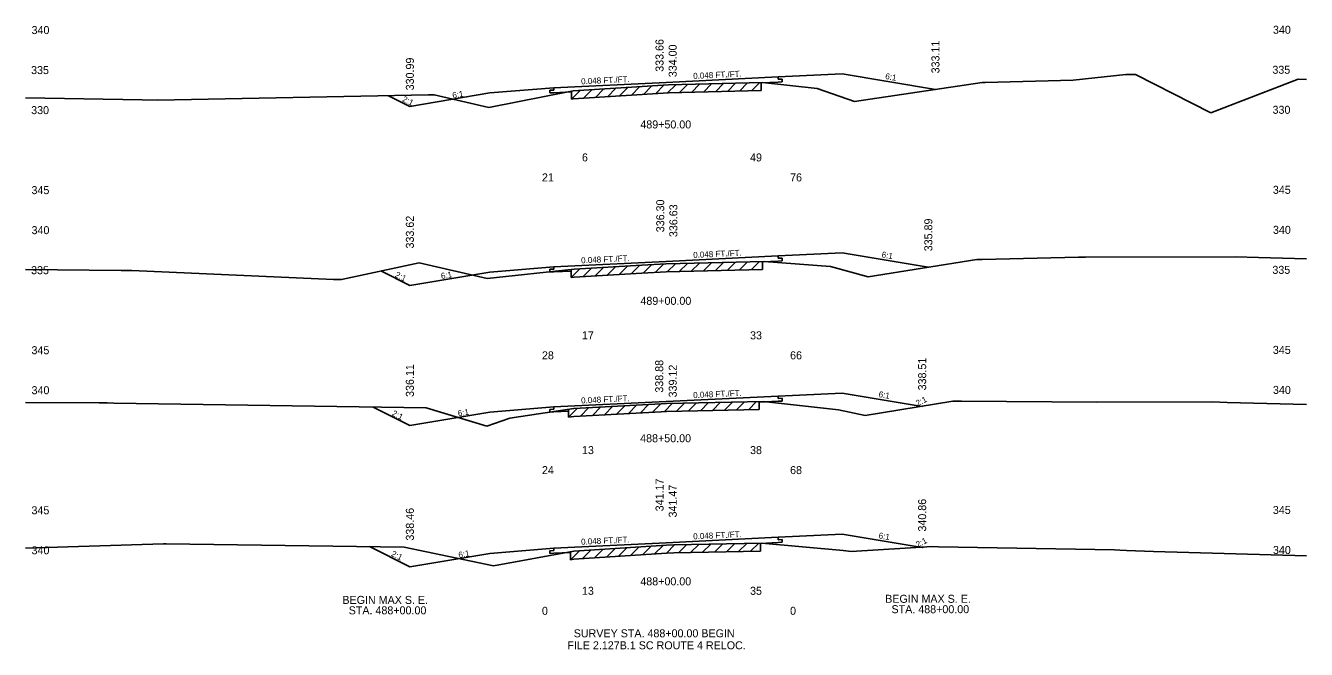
# Model space of a CAD drawing. Extents: x 2967 to 4323, y -3677 to -817.
# Drawn here: x 3188.8 to 3348.8, y -3676.7 to -3598.8 of the extents above; entities that cross this region are included whole.
import ezdxf

# ---------------------------------------------------------------- set-up
doc = ezdxf.new("R2010")
doc.units = 0
for name, color, linetype in [('Level 1', 7, 'Continuous'), ('Level 10', 7, 'Continuous'), ('Level 11', 7, 'Continuous'), ('Level 12', 7, 'Continuous'), ('Level 3', 7, 'Continuous'), ('Level 32', 7, 'Continuous'), ('Level 33', 7, 'Continuous'), ('Level 59', 7, 'Continuous'), ('Level 6', 7, 'Continuous'), ('Level 60', 7, 'Continuous'), ('Level 61', 7, 'Continuous'), ('Level 7', 7, 'Continuous')]:
    doc.layers.add(name, color=color, linetype=linetype)

msp = doc.modelspace()

# ---------------------------------------------------------------- linework, layer by layer
at = {"layer": 'Level 11'}
for p, q in [((3282.76, -3605.47), (3282.76, -3605.17)), ((3283.26, -3605.45), (3282.76, -3605.47)), ((3282.76, -3605.81), (3283.26, -3605.79)), ((3283.26, -3605.79), (3283.26, -3605.45)), ((3254.76, -3606.82), (3254.26, -3606.84)), ((3254.26, -3606.84), (3254.26, -3607.18)), ((3254.26, -3607.18), (3254.76, -3607.16)), ((3254.76, -3606.52), (3254.76, -3606.82)), ((3282.76, -3627.84), (3282.76, -3627.54)), ((3283.26, -3627.82), (3282.76, -3627.84)), ((3282.76, -3628.18), (3283.26, -3628.16)), ((3283.26, -3628.16), (3283.26, -3627.82)), ((3254.76, -3629.19), (3254.26, -3629.21)), ((3254.26, -3629.21), (3254.26, -3629.55)), ((3254.26, -3629.55), (3254.76, -3629.53)), ((3254.76, -3628.89), (3254.76, -3629.19)), ((3254.76, -3646.4), (3254.76, -3646.7)), ((3282.76, -3645.35), (3282.76, -3645.05)), ((3283.26, -3645.33), (3282.76, -3645.35)), ((3282.76, -3645.69), (3283.26, -3645.67)), ((3283.26, -3645.67), (3283.26, -3645.33)), ((3254.76, -3646.7), (3254.26, -3646.72)), ((3254.26, -3646.72), (3254.26, -3647.06)), ((3254.26, -3647.06), (3254.76, -3647.04)), ((3282.76, -3663), (3282.76, -3662.7)), ((3283.26, -3662.98), (3282.76, -3663)), ((3282.76, -3663.34), (3283.26, -3663.32)), ((3283.26, -3663.32), (3283.26, -3662.98)), ((3254.76, -3664.34), (3254.26, -3664.37)), ((3254.26, -3664.37), (3254.26, -3664.71)), ((3254.26, -3664.71), (3254.76, -3664.68)), ((3254.76, -3664.04), (3254.76, -3664.34))]:
    msp.add_line(p, q, dxfattribs=at)
at = {"layer": 'Level 12'}
for p, q in [((3280.65, -3605.91), (3282.76, -3605.81)), ((3280.65, -3605.89), (3280.65, -3605.91)), ((3256.94, -3607.05), (3254.76, -3607.16)), ((3256.94, -3606.96), (3256.94, -3607.05)), ((3280.83, -3628.28), (3282.76, -3628.18)), ((3280.83, -3628.24), (3280.83, -3628.28)), ((3256.9, -3629.43), (3254.76, -3629.53)), ((3256.9, -3629.22), (3256.9, -3629.43)), ((3280.4, -3645.81), (3282.76, -3645.69)), ((3280.4, -3645.74), (3280.4, -3645.81)), ((3256.56, -3646.95), (3254.76, -3647.04)), ((3256.56, -3646.7), (3256.56, -3646.95)), ((3280.56, -3663.45), (3282.76, -3663.34)), ((3280.56, -3663.42), (3280.56, -3663.45)), ((3256.82, -3664.58), (3254.76, -3664.68)), ((3256.82, -3664.5), (3256.82, -3664.58))]:
    msp.add_line(p, q, dxfattribs=at)
at = {"layer": 'Level 59'}
for p, q in [((3254.76, -3606.52), (3268.76, -3605.85)), ((3268.76, -3605.85), (3282.76, -3605.17)), ((3254.76, -3628.89), (3268.76, -3628.22)), ((3268.76, -3628.22), (3282.76, -3627.54)), ((3254.76, -3646.4), (3268.76, -3645.73)), ((3268.76, -3645.73), (3282.76, -3645.05)), ((3254.76, -3664.04), (3268.76, -3663.37)), ((3268.76, -3663.37), (3282.76, -3662.7))]:
    msp.add_line(p, q, dxfattribs=at)
at = {"layer": 'Level 6'}
for p, q in [((3282.76, -3605.17), (3290.76, -3604.79)), ((3246.76, -3607.18), (3254.76, -3606.52)), ((3282.76, -3627.54), (3290.76, -3627.16)), ((3246.76, -3629.56), (3254.76, -3628.89)), ((3282.76, -3645.05), (3290.76, -3644.67)), ((3246.76, -3647.06), (3254.76, -3646.4)), ((3282.76, -3662.7), (3290.76, -3662.32)), ((3246.76, -3664.71), (3254.76, -3664.04))]:
    msp.add_line(p, q, dxfattribs=at)
at = {"layer": 'Level 60'}
for p, q in [((3257.17, -3606.91), (3269.05, -3606.17)), ((3269.05, -3606.17), (3280.81, -3605.88)), ((3280.81, -3605.88), (3287.64, -3606.63)), ((3292.29, -3608.23), (3308.25, -3605.87)), ((3308.25, -3605.87), (3308.64, -3605.86)), ((3308.64, -3605.86), (3319.64, -3605.57)), ((3319.64, -3605.57), (3326.22, -3604.88)), ((3326.22, -3604.88), (3327.39, -3604.88)), ((3327.39, -3604.88), (3336.82, -3609.67)), ((3336.82, -3609.67), (3347.75, -3605.45)), ((3347.75, -3605.45), (3348.76, -3605.48)), ((3188.76, -3607.77), (3203.33, -3608.05)), ((3205.24, -3608.08), (3239.1, -3607.42)), ((3239.1, -3607.42), (3239.78, -3607.42)), ((3239.78, -3607.42), (3246.64, -3609.01)), ((3246.64, -3609.01), (3257.17, -3606.91)), ((3287.64, -3606.63), (3292.29, -3608.23)), ((3203.33, -3608.05), (3205.24, -3608.08)), ((3228.22, -3630.47), (3237.93, -3628.4)), ((3237.93, -3628.4), (3246.42, -3630.35)), ((3257.3, -3629.18), (3265.73, -3628.71)), ((3265.73, -3628.71), (3268.76, -3628.54)), ((3268.76, -3628.54), (3281.02, -3628.23)), ((3281.02, -3628.23), (3289.32, -3628.85)), ((3294, -3630.17), (3307.57, -3627.98)), ((3307.57, -3627.98), (3308.27, -3627.98)), ((3308.27, -3627.98), (3320.3, -3627.69)), ((3320.3, -3627.69), (3321.15, -3627.69)), ((3321.15, -3627.69), (3339.9, -3627.64)), ((3339.9, -3627.64), (3342.76, -3627.72)), ((3342.76, -3627.72), (3348.76, -3627.91)), ((3188.76, -3629.22), (3200.71, -3629.36)), ((3200.71, -3629.36), (3202.03, -3629.38)), ((3202.03, -3629.38), (3227.21, -3630.49)), ((3246.42, -3630.35), (3257.3, -3629.18)), ((3289.32, -3628.85), (3294, -3630.17)), ((3227.21, -3630.49), (3228.22, -3630.47)), ((3188.76, -3645.85), (3197.95, -3645.9)), ((3197.95, -3645.9), (3198.93, -3645.91)), ((3198.93, -3645.91), (3199.76, -3645.95)), ((3199.76, -3645.95), (3238.81, -3646.54)), ((3257.25, -3646.6), (3268.17, -3646)), ((3268.17, -3646), (3268.81, -3645.96)), ((3268.81, -3645.96), (3280.92, -3645.73)), ((3280.92, -3645.73), (3290.31, -3646.75)), ((3293.63, -3647.49), (3304.58, -3645.67)), ((3304.58, -3645.67), (3305.24, -3645.68)), ((3305.24, -3645.68), (3305.67, -3645.68)), ((3305.67, -3645.68), (3322.6, -3645.8)), ((3322.6, -3645.8), (3336.97, -3645.79)), ((3336.97, -3645.79), (3338.86, -3645.84)), ((3338.86, -3645.84), (3348.76, -3646.12)), ((3238.81, -3646.54), (3246.39, -3648.8)), ((3246.39, -3648.8), (3249.27, -3647.82)), ((3249.27, -3647.82), (3257.25, -3646.6)), ((3290.31, -3646.75), (3293.63, -3647.49)), ((3188.76, -3664.07), (3205.98, -3663.52)), ((3205.98, -3663.52), (3206.31, -3663.53)), ((3206.31, -3663.53), (3236.06, -3663.92)), ((3236.06, -3663.92), (3247.19, -3666.28)), ((3257.24, -3664.42), (3268.81, -3663.67)), ((3268.81, -3663.67), (3269.72, -3663.65)), ((3269.72, -3663.65), (3280.75, -3663.41)), ((3280.75, -3663.41), (3290.91, -3664.36)), ((3291.91, -3664.46), (3302.03, -3663.84)), ((3302.03, -3663.84), (3302.79, -3663.87)), ((3302.79, -3663.87), (3324.78, -3664.28)), ((3247.19, -3666.28), (3257.24, -3664.42)), ((3290.91, -3664.36), (3291.91, -3664.46)), ((3324.78, -3664.28), (3325.46, -3664.32)), ((3325.46, -3664.32), (3326.29, -3664.33)), ((3326.29, -3664.33), (3329.65, -3664.46)), ((3329.65, -3664.46), (3348.76, -3665.01))]:
    msp.add_line(p, q, dxfattribs=at)
at = {"layer": 'Level 61'}
for p, q in [((3265.5, -3606.39), (3264.44, -3607.46)), ((3267, -3606.3), (3265.94, -3607.37)), ((3268.5, -3606.21), (3267.44, -3607.27)), ((3269.97, -3606.15), (3268.94, -3607.18)), ((3271.46, -3606.11), (3270.44, -3607.14)), ((3272.96, -3606.08), (3271.94, -3607.1)), ((3274.46, -3606.04), (3273.44, -3607.06)), ((3275.96, -3606), (3274.94, -3607.03)), ((3277.46, -3605.97), (3276.44, -3606.99)), ((3278.96, -3605.93), (3277.94, -3606.95)), ((3280.46, -3605.89), (3279.44, -3606.92)), ((3280.65, -3606.89), (3280.65, -3605.89)), ((3258.04, -3606.86), (3256.94, -3607.96)), ((3256.94, -3606.96), (3256.94, -3607.96)), ((3256.94, -3607.96), (3257.17, -3607.91)), ((3257.17, -3607.91), (3269.05, -3607.17)), ((3259.5, -3606.77), (3258.44, -3607.83)), ((3261, -3606.67), (3259.94, -3607.74)), ((3262.5, -3606.58), (3261.44, -3607.65)), ((3264, -3606.49), (3262.94, -3607.55)), ((3269.05, -3607.17), (3280.65, -3606.89)), ((3265.46, -3628.73), (3264.4, -3629.79)), ((3266.96, -3628.64), (3265.9, -3629.7)), ((3268.46, -3628.56), (3267.4, -3629.62)), ((3269.93, -3628.51), (3268.9, -3629.54)), ((3271.43, -3628.48), (3270.4, -3629.5)), ((3272.93, -3628.44), (3271.9, -3629.46)), ((3274.43, -3628.4), (3273.4, -3629.43)), ((3275.93, -3628.36), (3274.9, -3629.39)), ((3277.43, -3628.32), (3276.4, -3629.35)), ((3278.93, -3628.29), (3277.9, -3629.31)), ((3280.43, -3628.25), (3279.4, -3629.27)), ((3280.83, -3629.24), (3280.83, -3628.24)), ((3257.98, -3629.14), (3256.9, -3630.22)), ((3256.9, -3629.22), (3256.9, -3630.22)), ((3256.9, -3630.22), (3257.3, -3630.18)), ((3257.3, -3630.18), (3265.73, -3629.71)), ((3259.46, -3629.06), (3258.4, -3630.12)), ((3260.96, -3628.98), (3259.9, -3630.04)), ((3262.46, -3628.89), (3261.4, -3629.95)), ((3263.96, -3628.81), (3262.9, -3629.87)), ((3265.73, -3629.71), (3268.76, -3629.54)), ((3268.76, -3629.54), (3280.83, -3629.24)), ((3262.12, -3646.33), (3261.06, -3647.39)), ((3263.62, -3646.25), (3262.56, -3647.3)), ((3265.12, -3646.16), (3264.06, -3647.22)), ((3266.62, -3646.08), (3265.56, -3647.14)), ((3268.12, -3646), (3267.06, -3647.06)), ((3269.59, -3645.95), (3268.56, -3646.97)), ((3271.08, -3645.92), (3270.06, -3646.94)), ((3272.58, -3645.89), (3271.56, -3646.91)), ((3274.08, -3645.86), (3273.06, -3646.88)), ((3275.58, -3645.83), (3274.56, -3646.85)), ((3277.08, -3645.8), (3276.06, -3646.82)), ((3278.58, -3645.77), (3277.56, -3646.79)), ((3280.08, -3645.74), (3279.06, -3646.76)), ((3280.4, -3646.74), (3280.4, -3645.74)), ((3257.69, -3646.57), (3256.56, -3647.7)), ((3256.56, -3646.7), (3256.56, -3647.7)), ((3256.56, -3647.7), (3257.25, -3647.6)), ((3257.25, -3647.6), (3268.17, -3647)), ((3259.12, -3646.49), (3258.06, -3647.55)), ((3260.62, -3646.41), (3259.56, -3647.47)), ((3268.17, -3647), (3268.81, -3646.96)), ((3268.81, -3646.96), (3280.4, -3646.74)), ((3263.89, -3663.99), (3262.82, -3665.06)), ((3265.39, -3663.89), (3264.32, -3664.96)), ((3266.89, -3663.8), (3265.82, -3664.87)), ((3268.39, -3663.7), (3267.32, -3664.77)), ((3269.84, -3663.65), (3268.82, -3664.67)), ((3271.34, -3663.62), (3270.32, -3664.64)), ((3272.84, -3663.59), (3271.82, -3664.61)), ((3274.34, -3663.55), (3273.32, -3664.57)), ((3275.84, -3663.52), (3274.82, -3664.54)), ((3277.34, -3663.49), (3276.32, -3664.51)), ((3278.84, -3663.45), (3277.82, -3664.48)), ((3280.34, -3663.42), (3279.32, -3664.44)), ((3280.56, -3664.42), (3280.56, -3663.42)), ((3257.94, -3664.37), (3256.82, -3665.5)), ((3256.82, -3664.5), (3256.82, -3665.5)), ((3256.82, -3665.5), (3257.24, -3665.42)), ((3257.24, -3665.42), (3268.81, -3664.67)), ((3259.39, -3664.28), (3258.32, -3665.35)), ((3260.89, -3664.18), (3259.82, -3665.25)), ((3262.39, -3664.09), (3261.32, -3665.16)), ((3268.81, -3664.67), (3269.72, -3664.65)), ((3269.72, -3664.65), (3280.56, -3664.42))]:
    msp.add_line(p, q, dxfattribs=at)
at = {"layer": 'Level 7'}
for p, q in [((3290.76, -3604.79), (3302.42, -3606.73)), ((3234.09, -3607.52), (3236.76, -3608.85)), ((3236.76, -3608.85), (3246.76, -3607.18)), ((3290.76, -3627.16), (3301.53, -3628.96)), ((3233.15, -3629.42), (3236.76, -3631.22)), ((3236.76, -3631.22), (3246.76, -3629.56)), ((3290.76, -3644.67), (3300.76, -3646.34)), ((3300.76, -3646.34), (3300.86, -3646.29)), ((3232.17, -3646.44), (3236.76, -3648.73)), ((3236.76, -3648.73), (3246.76, -3647.06)), ((3290.76, -3662.32), (3300.76, -3663.98)), ((3231.73, -3663.86), (3236.76, -3666.38)), ((3300.76, -3663.98), (3300.89, -3663.91)), ((3236.76, -3666.38), (3246.76, -3664.71))]:
    msp.add_line(p, q, dxfattribs=at)

# ---------------------------------------------------------------- texts
at = {"layer": 'Level 1'}
for s, p in [('6', (3258.26, -3615.73)), ('49', (3279.26, -3615.73)), ('21', (3253.26, -3618.23)), ('76', (3284.26, -3618.23)), ('17', (3258.26, -3637.96)), ('33', (3279.26, -3637.96)), ('28', (3253.26, -3640.46)), ('66', (3284.26, -3640.46)), ('13', (3258.26, -3652.3)), ('38', (3279.26, -3652.3)), ('24', (3253.26, -3654.8)), ('68', (3284.26, -3654.8)), ('BEGIN MAX S. E.', (3228.33, -3671.02)), ('13', (3258.26, -3669.88)), ('35', (3279.26, -3669.88)), ('BEGIN MAX S. E.', (3296.14, -3670.88)), ('STA. 488+00.00', (3229.12, -3672.32)), ('0', (3253.26, -3672.38)), ('0', (3284.26, -3672.38)), ('STA. 488+00.00', (3296.93, -3672.18)), ('SURVEY STA. 488+00.00 BEGIN', (3257.23, -3675.19)), (' FILE 2.127B.1 SC ROUTE 4 RELOC.', (3256.06, -3676.69))]:
    msp.add_text(s, height=1, dxfattribs=at).set_placement(p)
at = {"layer": 'Level 10'}
for s, p in [('333.66', (3268.45, -3604.53)), ('336.30', (3268.54, -3624.58)), ('338.88', (3268.41, -3644.62)), ('341.17', (3268.45, -3659.45))]:
    msp.add_text(s, height=1, rotation=90, dxfattribs=at).set_placement(p)
for s, p in [('489+50.00', (3265.55, -3611.61)), ('489+00.00', (3265.56, -3633.65)), ('488+50.00', (3265.53, -3650.82)), ('488+00.00', (3265.55, -3668.7))]:
    msp.add_text(s, height=1, dxfattribs=at).set_placement(p)
at = {"layer": 'Level 3'}
for s, p in [(' 340', (3189.13, -3599.82)), (' 340', (3344.21, -3599.78)), (' 335', (3189.07, -3604.82)), (' 335', (3344.14, -3604.78)), (' 330', (3189.08, -3609.82)), (' 330', (3344.16, -3609.78)), (' 345', (3189.12, -3619.82)), (' 345', (3344.2, -3619.78)), (' 340', (3189.13, -3624.82)), (' 340', (3344.21, -3624.78)), (' 335', (3344.14, -3629.78)), (' 335', (3189.07, -3629.82)), (' 345', (3189.12, -3639.82)), (' 345', (3344.2, -3639.78)), (' 340', (3189.13, -3644.82)), (' 340', (3344.21, -3644.78)), (' 345', (3189.12, -3659.82)), (' 345', (3344.2, -3659.78)), (' 340', (3189.13, -3664.82)), (' 340', (3344.21, -3664.78))]:
    msp.add_text(s, height=1, dxfattribs=at).set_placement(p)
at = {"layer": 'Level 32'}
for s, rotation, p in [('0.048 FT./FT.', 2.748, (3272.17, -3605.43)), ('6:1', 350.5377, (3296.11, -3605.43)), ('0.048 FT./FT.', 2.7481, (3258.17, -3606.1)), ('2:1', 333.435, (3235.74, -3608.19)), ('6:1', 9.4623, (3242.13, -3607.86)), ('0.048 FT./FT.', 2.748, (3272.17, -3627.8)), ('6:1', 350.5377, (3295.66, -3627.72)), ('0.048 FT./FT.', 2.7481, (3258.17, -3628.47)), ('2:1', 333.435, (3234.84, -3630.14)), ('6:1', 9.4623, (3240.71, -3630.43)), ('0.048 FT./FT.', 2.748, (3272.17, -3645.31)), ('6:1', 350.5377, (3295.28, -3645.17)), ('0.048 FT./FT.', 2.7481, (3258.17, -3645.98)), ('2:1', 26.5651, (3300.19, -3646.34)), ('2:1', 333.435, (3234.44, -3647.44)), ('6:1', 9.4623, (3242.82, -3647.59)), ('0.048 FT./FT.', 2.7481, (3272.17, -3662.96)), ('6:1', 350.5377, (3295.28, -3662.82)), ('0.048 FT./FT.', 2.7481, (3258.17, -3663.63)), ('2:1', 26.5651, (3300.21, -3663.98)), ('2:1', 333.435, (3234.35, -3665)), ('6:1', 9.4623, (3242.89, -3665.27))]:
    msp.add_text(s, height=0.75, rotation=rotation, dxfattribs=at).set_placement(p)
at = {"layer": 'Level 33'}
for s, p in [('333.11', (3302.92, -3604.73)), ('330.99', (3237.26, -3606.85)), ('333.62', (3237.26, -3626.61)), ('335.89', (3302.03, -3626.96)), ('336.11', (3237.26, -3645.16)), ('338.51', (3301.26, -3644.34)), ('338.46', (3237.26, -3663.11)), ('340.86', (3301.26, -3661.98))]:
    msp.add_text(s, height=1, rotation=90, dxfattribs=at).set_placement(p)
at = {"layer": 'Level 59'}
for s, p in [(' 334.00', (3270.09, -3605.58)), (' 336.63', (3270.18, -3625.56)), (' 339.12', (3270.1, -3645.59)), (' 341.47', (3270.1, -3660.59))]:
    msp.add_text(s, height=1, rotation=90, dxfattribs=at).set_placement(p)

doc.saveas('drawing.dxf')
